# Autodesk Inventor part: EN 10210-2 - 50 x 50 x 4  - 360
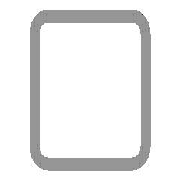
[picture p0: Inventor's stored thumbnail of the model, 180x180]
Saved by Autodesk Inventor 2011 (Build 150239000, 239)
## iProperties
IsCustomPart: 1
Created: 2010-02
Part Number: EN 10210-2 - 50 x 50 x 4  - 360
Material: Steel, Mild
Description: Tube 50*50*4
Document SubType Name: Modeling
Standard: DIN
Designer: PC
Standard Revision: 1997
Standards Organization: DIN
Language: en-US
Size Designation: 50 x 50 x 4
Categories: <MemberInstance><Categories><Category DisplayName="Structural Shapes" InternalName="089c4875-fa83-4c05-b084-43b9cc11f5ed" Mnemonic="GRDR"><CategoryParameter Dis
Stock Number: 50 x 50 x 4
Density: 7.86 g/cm^3
_CCFamilyMember: 15
_CCFamilyDisplayName: DIN EN 10219-2 (Square Hollow Section - Cold Formed) - Cold formed welded structural hollow sections of non-alloy and fine grain structural steel
_FrameMemberDoc: Frame Member File
_Version: 15.0.0
_GetPNFromCC: 1
G_L: 360.000 mm
G_W: 50.000 mm
G_H: 50.000 mm
+C9EA426D-D9F7-4518-AD77-3C4FC1C949F9+CUTDETAIL1: Miter 45.00 deg
Author: PC
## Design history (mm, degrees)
node "Start plane"
node "End plane"
sketch "Sketch"
  geometry: L1 (-25, -17)-(-25, 17); L2 (-17, 25)-(17, 25); L3 (25, 17)-(25, -17); L4 (17, -25)-(-17, -25); L5 (-17, 21)-(17, 21); L6 (21, 17)-(21, -17); L7 (17, -21)-(-17, -21); L8 (-21, -17)-(-21, 17); L9 (0, 37.32)-(0, -37.32) reference; L10 (-37.32, 0)-(37.32, 0) reference; A1 r 8 centre (-17, -17) between (-25, -17) and (-17, -25); A2 r 8 centre (-17, 17) between (-17, 25) and (-25, 17); A3 r 8 centre (17, 17) between (25, 17) and (17, 25); A4 r 8 centre (17, -17) between (17, -25) and (25, -17); A5 r 4 centre (-17, 17) between (-17, 21) and (-21, 17); A6 r 4 centre (17, 17) between (21, 17) and (17, 21); A7 r 4 centre (17, -17) between (17, -21) and (21, -17); A8 r 4 centre (-17, -17) between (-21, -17) and (-17, -21)
  constraints: 16 end point, 16 point on circle, 8 centre point, 8 tangent, 4 parallel, 3 equal radius, 2 perpendicular, 7 other
  dimensions: "d7" = 8 radius of A1 (= G_IR); "d10" = 50 distance between parallel lines of L2 L4 (= G_H); "d11" = 50 distance between parallel lines of L1 L3 (= G_W); "d12" = 4 distance between parallel lines of L3 L6 (= G_T); "d15" = 25 distance between parallel lines of L2 L10 (= 0.5 x d10); "d16" = 25 distance between parallel lines of L9 L3 (= 0.5 x d11)
extrude "Body" new body sketch "Sketch" stored distance "d3" = 360 (= G_L); taper "d4" = 0 deg
node "Driven Length"
  sketch "Sketch3"
    geometry: L1 (0, 0)-(10, 0) reference
    constraints: 2 end point, 1 horizontal
  workplane "Work Plane3"
  sketch "Sketch4"
    geometry: L1 (-2, 0)-(12, 0) reference; L2 (-2, 360)-(12, 360) reference
    dimensions: "d18" = 360 distance between parallel lines of L1 L2 (derived)
workplane "Work Plane4"
split "Split1"
body "Solid1"
other parameters: "G_W" = 50 [user parameter; used in 1 equation term], "G_H" = 50 [user parameter; used in 1 equation term], "G_T" = 4 [user parameter; used in 1 equation term], "G_IR" = 8 [user parameter; used in 1 equation term], "G_L" = 360 (= d18) [user parameter; used in 1 equation term], "G_OFFSET_START" = 0 [user parameter; used in 1 equation term], "G_OFFSET_END" = 0 [user parameter; used in 1 equation term], "d13" = 0 (computed from G_OFFSET_START), "d17" = 90 deg
